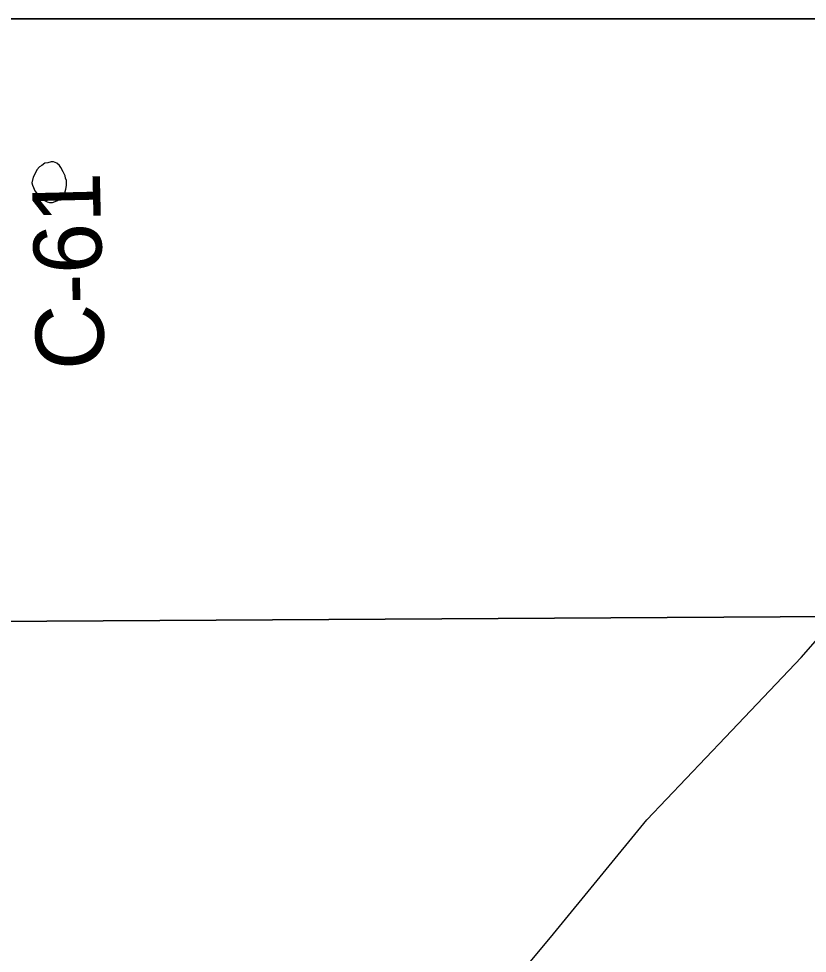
# Model space of a CAD drawing. Extents: x 0 to 34, y 0 to 22.
# Drawn here: x 3.351 to 4.009, y 20.12 to 20.9 of the extents above; entities that cross this region are included whole.
import ezdxf

# ---------------------------------------------------------------- set-up
doc = ezdxf.new("R2010")
doc.units = 0
for name, color, linetype in [('GM_X_Corporation', 7, 'Continuous'), ('GM_X_County_Road_Text', 7, 'Continuous'), ('GM_X_Minor_Lake', 7, 'Continuous'), ('GM_X_Township_Road', 7, 'Continuous'), ('SH_Data', 7, 'Continuous')]:
    doc.layers.add(name, color=color, linetype=linetype)

msp = doc.modelspace()

# ---------------------------------------------------------------- linework, layer by layer
at = {"layer": 'GM_X_Corporation'}
for points in [[(6.97994, 20.9), (2.1, 20.9)], [(6.97994, 20.9), (2.1, 20.9)], [(5.94533, 20.41578), (5.00335, 20.41162), (4.03341, 20.40117), (3.32712, 20.397)], [(3.32712, 20.397), (4.03341, 20.40117), (5.00335, 20.41162), (5.94533, 20.41578)], [(5.94533, 20.41578), (5.00335, 20.41162), (4.03341, 20.40117), (3.32712, 20.397)], [(3.32712, 20.397), (4.03341, 20.40117), (5.00335, 20.41162), (5.94533, 20.41578)]]:
    msp.add_lwpolyline(points, dxfattribs=at)
at = {"layer": 'GM_X_Minor_Lake'}
for points in [[(3.36509, 20.77205), (3.36306, 20.76788), (3.36197, 20.76292), (3.36237, 20.76102), (3.36315, 20.75913), (3.36432, 20.75648), (3.36625, 20.75383), (3.36779, 20.75157), (3.36971, 20.74968), (3.37238, 20.74819), (3.37468, 20.74707), (3.37658, 20.74671), (3.37924, 20.74674), (3.38265, 20.74791), (3.38529, 20.74985), (3.38718, 20.75139), (3.38905, 20.75369), (3.39015, 20.75789), (3.39088, 20.76094), (3.39084, 20.76513), (3.39006, 20.76702), (3.38966, 20.76892), (3.38811, 20.77233), (3.38617, 20.77573), (3.38501, 20.77762), (3.38272, 20.7795), (3.38004, 20.78062)], [(3.38004, 20.78062), (3.37814, 20.78059), (3.37511, 20.7798), (3.37283, 20.7794), (3.37019, 20.77747), (3.3683, 20.7763), (3.36605, 20.774), (3.36509, 20.77205)]]:
    msp.add_lwpolyline(points, dxfattribs=at)
at = {"layer": 'GM_X_Township_Road'}
msp.add_lwpolyline([(3.587, 19.87766), (3.59832, 19.89128), (3.63661, 19.94339), (3.79742, 20.13645), (3.87514, 20.23153), (3.94088, 20.30057), (4.00413, 20.36713), (4.03363, 20.40062)], dxfattribs=at)
at = {"layer": 'SH_Data'}
msp.add_line((2.1, 20.9), (8.9, 20.9), dxfattribs=at)

# ---------------------------------------------------------------- texts
at = {"layer": 'GM_X_County_Road_Text'}
msp.add_text('C-61', height=0.056818, rotation=91.3839, dxfattribs=at).set_placement((3.42256, 20.60761))

doc.saveas('drawing.dxf')
